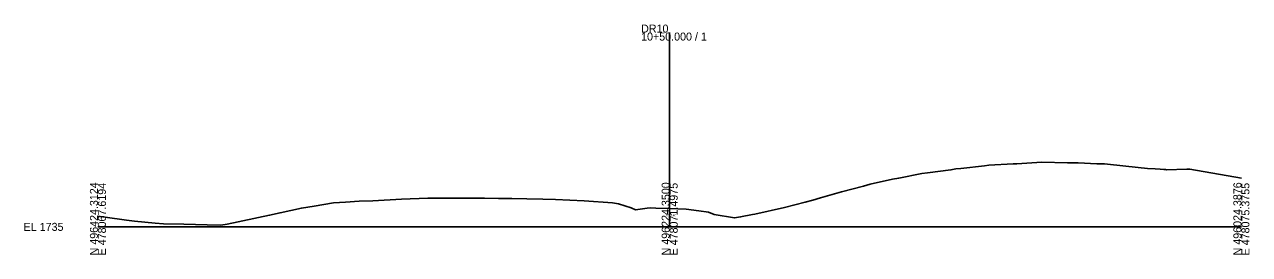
# Model space of a CAD drawing. Extents: x -26 to 403, y -10 to 2062.
# Drawn here: x -25.7 to 402.8, y 490.3 to 570.9 of the extents above; entities that cross this region are included whole.
import ezdxf

# ---------------------------------------------------------------- set-up
doc = ezdxf.new("R2010")
doc.units = 0
for name, color, linetype in [('Exist Cross Section Cell', 7, 'Continuous'), ('Exist XS Center Line Elevation Label', 7, 'Continuous'), ('Exist XS Ground Line', 7, 'Continuous'), ('Scratch_Level_5', 7, 'Continuous')]:
    doc.layers.add(name, color=color, linetype=linetype)

msp = doc.modelspace()

# ---------------------------------------------------------------- linework, layer by layer
at = {"layer": 'Exist Cross Section Cell'}
for p, q in [((200, 500), (200, 568.05)), ((0, 500), (200, 500)), ((200, 500), (400, 500))]:
    msp.add_line(p, q, dxfattribs=at)
at = {"layer": 'Exist XS Ground Line'}
msp.add_lwpolyline([(0, 503.78), (2.55, 503.37), (10.03, 502.29), (12.76, 502.01), (20.04, 501.27), (22.96, 501.09), (30.04, 500.99), (38.19, 500.74), (42.94, 500.55), (45.16, 500.92), (60.05, 504.04), (63.7, 504.94), (71.19, 506.57), (75.67, 507.27), (82.36, 508.36), (86.59, 508.6), (91.4, 508.99), (96.13, 509.13), (106.14, 509.72), (115.37, 510), (120.08, 510.02), (124.97, 510.02), (130.08, 510), (135.18, 510.02), (140.08, 509.99), (144.81, 509.93), (150.09, 509.8), (155.58, 509.73), (160.09, 509.62), (170.12, 509.07), (179.96, 508.39), (182.05, 508.01), (186.59, 506.61), (188.09, 505.94), (192.16, 506.49), (193.27, 506.62), (195.12, 506.56), (200, 506.4), (205.81, 506.2), (210.24, 505.64), (213.58, 505.2), (215.59, 504.36), (222.68, 503.13), (224.05, 503.36), (224.83, 503.48), (228.94, 504.28), (229.76, 504.44), (240.12, 506.75), (247.39, 508.68), (250.13, 509.35), (252.75, 510.11), (260.13, 512.28), (267.8, 514.26), (270.13, 514.92), (278, 516.65), (280.14, 517.1), (288.2, 518.65), (290.14, 518.96), (298.4, 519.96), (300.15, 520.28), (301.82, 520.42), (310.15, 521.41), (311.64, 521.57), (320.15, 522.05), (321.45, 522.11), (330.16, 522.68), (339.21, 522.48), (342.91, 522.43), (349.41, 522.13), (352.14, 522.09), (359.61, 521.31), (367.16, 520.44), (369.81, 520.31), (371.57, 520.2), (372.82, 520.12), (373.43, 520.05), (373.75, 520.02), (380.9, 520.25), (381.91, 520.23), (400, 517.08)], dxfattribs=at)
at = {"layer": 'Scratch_Level_5'}
msp.add_lwpolyline([(0, 503.78), (2.55, 503.37), (10.03, 502.29), (12.76, 502.01), (20.04, 501.27), (22.96, 501.09), (30.04, 500.99), (38.19, 500.74), (42.94, 500.55), (45.16, 500.92), (60.05, 504.04), (63.7, 504.94), (71.19, 506.57), (75.67, 507.27), (82.36, 508.36), (86.59, 508.6), (91.4, 508.99), (96.13, 509.13), (106.14, 509.72), (115.37, 510), (120.08, 510.02), (124.97, 510.02), (130.08, 510), (135.18, 510.02), (140.08, 509.99), (144.81, 509.93), (150.09, 509.8), (155.58, 509.73), (160.09, 509.62), (170.12, 509.07), (179.96, 508.39), (182.05, 508.01), (186.59, 506.61), (188.09, 505.94), (192.16, 506.49), (193.27, 506.62), (195.12, 506.56), (200, 506.4), (205.81, 506.2), (210.24, 505.64), (213.58, 505.2), (215.59, 504.36), (222.68, 503.13), (224.05, 503.36), (224.83, 503.48), (228.94, 504.28), (229.76, 504.44), (240.12, 506.75), (247.39, 508.68), (250.13, 509.35), (252.75, 510.11), (260.13, 512.28), (267.8, 514.26), (270.13, 514.92), (278, 516.65), (280.14, 517.1), (288.2, 518.65), (290.14, 518.96), (298.4, 519.96), (300.15, 520.28), (301.82, 520.42), (310.15, 521.41), (311.64, 521.57), (320.15, 522.05), (321.45, 522.11), (330.16, 522.68), (339.21, 522.48), (342.91, 522.43), (349.41, 522.13), (352.14, 522.09), (359.61, 521.31), (367.16, 520.44), (369.81, 520.31), (371.57, 520.2), (372.82, 520.12), (373.75, 520.02)], dxfattribs=at)

# ---------------------------------------------------------------- texts
at = {"layer": 'Exist Cross Section Cell'}
for s, p in [('DR10', (190, 568.05)), ('10+50.000 / 1', (190, 565.25)), ('EL 1735', (-26, 498.6))]:
    msp.add_text(s, height=2.8, dxfattribs=at).set_placement(p)
for s, p in [('N 496424.3124', (0, 490)), ('E 478067.6194', (2.8, 490)), ('N 496224.3500', (200, 490)), ('E 478071.4975', (202.8, 490)), ('N 496024.3876', (400, 490)), ('E 478075.3755', (402.8, 490))]:
    msp.add_text(s, height=2.8, rotation=90, dxfattribs=at).set_placement(p)
at = {"layer": 'Exist XS Center Line Elevation Label'}
msp.add_text('1741.40', height=0.75, dxfattribs=at).set_placement((198.45, 503.65))

doc.saveas('drawing.dxf')
